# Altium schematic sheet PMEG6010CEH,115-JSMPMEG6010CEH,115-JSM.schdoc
size 127 x 101 mm
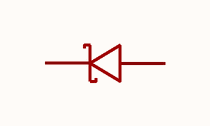
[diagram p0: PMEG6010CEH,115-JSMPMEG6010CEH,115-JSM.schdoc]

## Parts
D?  pmeg6010ceh,115-jsm  [SOD-123FL_L2.8-W1.7-LS3.6-RD]  (value not drawn)

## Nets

Not connected (* = marked no-connect by the designer): D? 1(C) 2(A)

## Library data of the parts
D? = pmeg6010ceh,115-jsm: 二极管配置:1个独立式;正向压降(Vf):850mV@1A;直流反向耐压(Vr):60V;整流电流:1A;; Manufacturer: JSMSEMI(杰盛微); AddInBom: yes; ModelId: b9b923f0a64d4b9fb554884131211b98; ModelTransform: 145.669,70.866,0,0,0,0,0,0,0; Diode Configuration: 1个独立式; Voltage - DC Reverse(Vr): 60V; Current - Rectified: 1A; Reverse Leakage Current (Ir): 250uA; Operating Junction Temperature Range: -55℃~+125℃; Non-Repetitive Peak Forward Surge Current: 25A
